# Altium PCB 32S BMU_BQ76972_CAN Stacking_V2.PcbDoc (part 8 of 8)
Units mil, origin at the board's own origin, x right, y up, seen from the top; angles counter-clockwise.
Board outline 7319.29 x 5216.54 mil, 4 copper layers (Top Layer, Layer 1, Layer 2, Bottom Layer), stack 73.068 mil thick; 811 components, 524 nets, 2320 pads, 2669 vias.
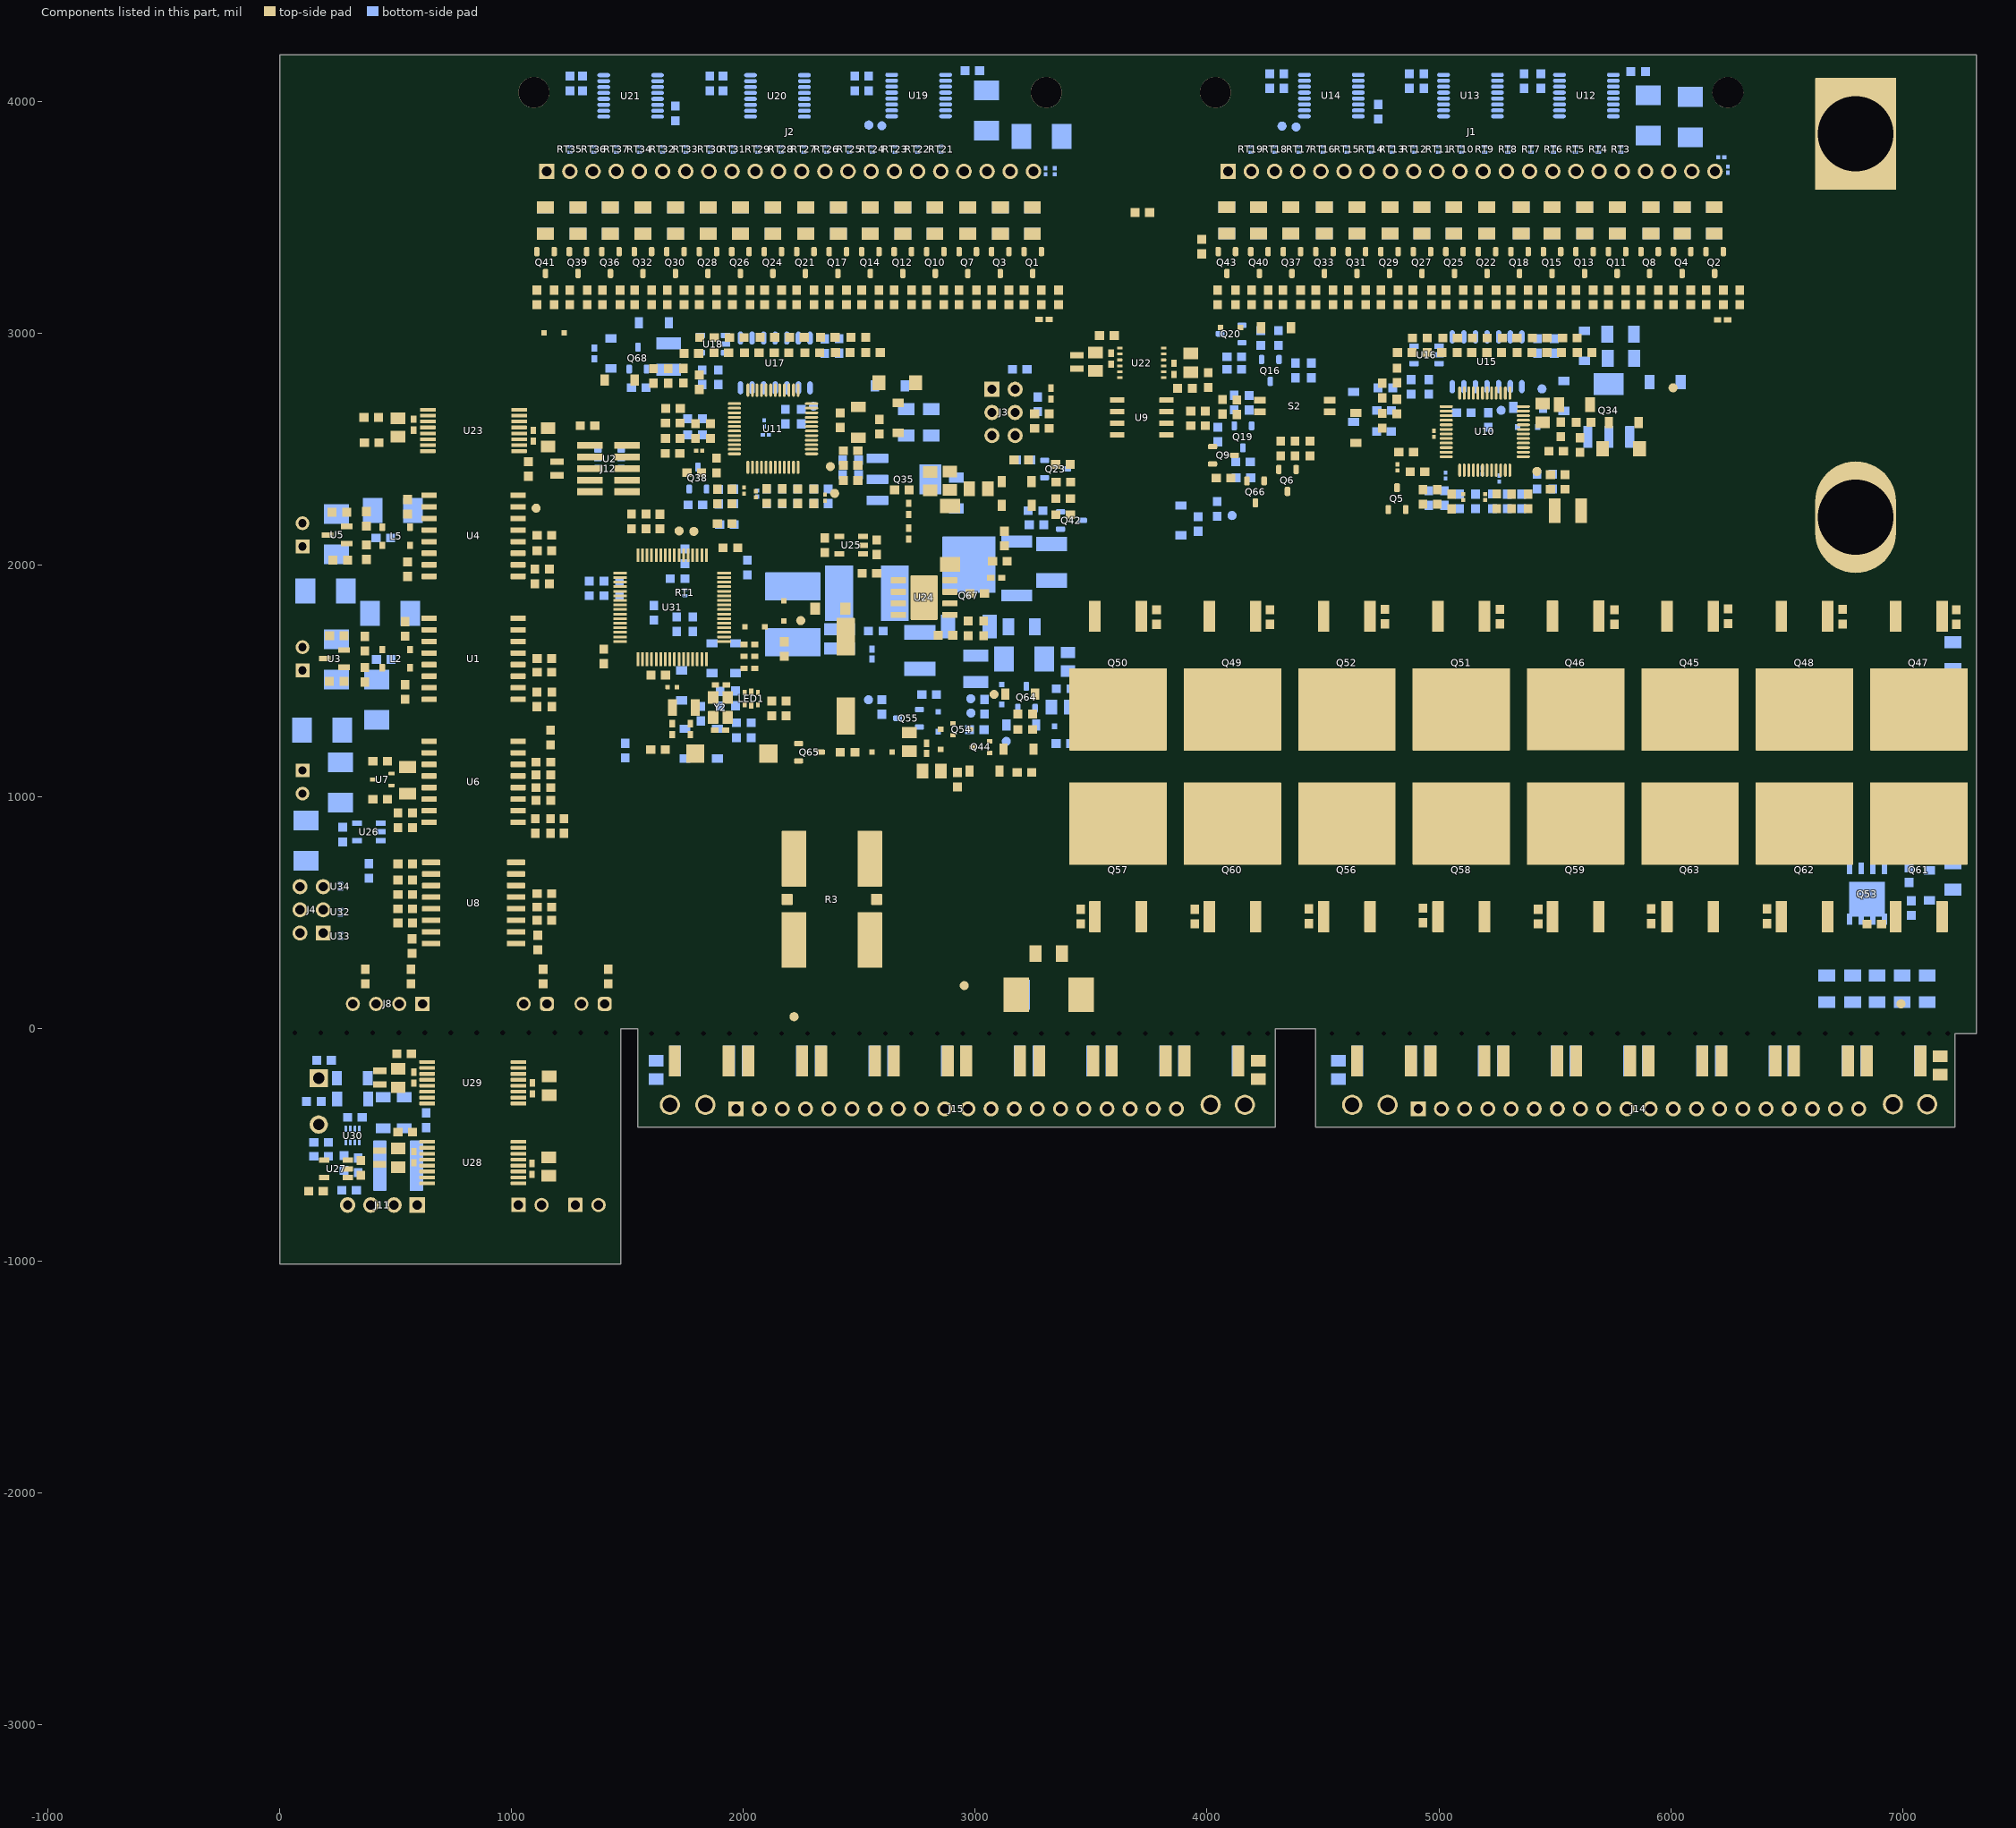
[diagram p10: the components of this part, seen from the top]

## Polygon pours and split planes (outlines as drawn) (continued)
NetQ8_3 on Bottom Layer "BOTTOM_LAYER_NETQ8_3_P371" (solid, remove dead copper, pour order 371): 6006.01,3285.78 5875.74,3285.78 5875.74,3481.81 6006.01,3481.81
NetQ4_3 on Bottom Layer "BOTTOM_LAYER_NETQ4_3_P372" (solid, remove dead copper, pour order 372): 6140.57,3285.78 6010.31,3285.78 6010.31,3481.81 6140.57,3481.81
NetQ2_3 on Bottom Layer "BOTTOM_LAYER_NETQ2_3_P373" (solid, remove dead copper, pour order 373): 6270.53,3285.78 6148.98,3285.78 6148.98,3481.81 6270.53,3481.81
Cell17 on Bottom Layer "BOTTOM_LAYER_CELL17_P389" (solid, remove dead copper, pour order 389): 4046.5,3651.57 4171.16,3651.57 4171.16,3504.92 4046.5,3504.92
Cell18 on Bottom Layer "BOTTOM_LAYER_CELL18_P390" (solid, remove dead copper, pour order 390): 4183.33,3651.57 4307.98,3651.57 4307.98,3504.92 4183.33,3504.92
Cell19 on Bottom Layer "BOTTOM_LAYER_CELL19_P391" (solid, remove dead copper, pour order 391): 4322.96,3651.57 4447.61,3651.57 4447.61,3504.92 4322.96,3504.92
Cell20 on Bottom Layer "BOTTOM_LAYER_CELL20_P392" (solid, remove dead copper, pour order 392): 4467.7,3651.57 4592.36,3651.57 4592.36,3504.92 4467.7,3504.92
Cell21 on Bottom Layer "BOTTOM_LAYER_CELL21_P393" (solid, remove dead copper, pour order 393): 4607.97,3651.57 4732.62,3651.57 4732.62,3504.92 4607.97,3504.92
Cell22 on Bottom Layer "BOTTOM_LAYER_CELL22_P394" (solid, remove dead copper, pour order 394): 4750.88,3651.57 4875.54,3651.57 4875.54,3504.92 4750.88,3504.92
Cell23 on Bottom Layer "BOTTOM_LAYER_CELL23_P409" (solid, remove dead copper, pour order 409): 4888.49,3651.57 5013.15,3651.57 5013.15,3504.92 4888.49,3504.92
Cell24 on Bottom Layer "BOTTOM_LAYER_CELL24_P415" (solid, remove dead copper, pour order 415): 5025.86,3651.57 5150.52,3651.57 5150.52,3504.92 5025.86,3504.92
Cell25 on Bottom Layer "BOTTOM_LAYER_CELL25_P416" (solid, remove dead copper, pour order 416): 5167.05,3651.57 5291.7,3651.57 5291.7,3504.92 5167.05,3504.92
Cell26 on Bottom Layer "BOTTOM_LAYER_CELL26_P420" (solid, remove dead copper, pour order 420): 5316.58,3651.57 5441.24,3651.57 5441.24,3504.92 5316.58,3504.92
Cell27 on Bottom Layer "BOTTOM_LAYER_CELL27_P427" (solid, remove dead copper, pour order 427): 5449.54,3616.02 5574.2,3616.02 5574.2,3504.92 5449.54,3504.92
Cell28 on Bottom Layer "BOTTOM_LAYER_CELL28_P434" (solid, remove dead copper, pour order 434): 5589.8,3616.02 5714.46,3616.02 5714.46,3504.92 5589.8,3504.92
Cell29 on Bottom Layer "BOTTOM_LAYER_CELL29_P445" (solid, remove dead copper, pour order 445): 5731.78,3616.02 5856.44,3616.02 5856.44,3504.92 5731.78,3504.92
Cell30 on Bottom Layer "BOTTOM_LAYER_CELL30_P459" (solid, remove dead copper, pour order 459): 5876.03,3616.02 6000.68,3616.02 6000.68,3504.92 5876.03,3504.92
Cell31 on Bottom Layer "BOTTOM_LAYER_CELL31_P466" (solid, remove dead copper, pour order 466): 6010.59,3616.02 6135.25,3616.02 6135.25,3504.92 6010.59,3504.92
Cell32 on Bottom Layer "BOTTOM_LAYER_CELL32_P468" (solid, remove dead copper, pour order 468): 6152.59,3620.67 6277.25,3620.67 6277.25,3509.57 6152.59,3509.57
Cell14 on Bottom Layer "BOTTOM_LAYER_CELL14_P386" (solid, remove dead copper, pour order 386): 2929.27,3615.04 3053.92,3615.04 3053.92,3494.09 2929.27,3494.09
5V_EXT on Bottom Layer "Bottom Layer-5V_EXT" (solid, remove dead copper, pour order 250): 631.98,-701.89 659.54,-674.33 659.54,-404.06 409.55,-404.06 409.55,-450.37 521.12,-561.94 521.12,-671.7 552.06,-702.63 552.06,-789.85 562.59,-800.38 628.18,-800.38 631.98,-796.58
GND_SYS_EXT on Bottom Layer "BOTTOM_LAYER_GND_SYS_EXT_P473" (solid, remove dead copper, pour order 473): 9.6,-39.88 664.29,-39.88 664.29,-994.6 9.25,-994.6
GND_EXT on Bottom Layer "BOTTOM_LAYER_GND_EXT_P474" (solid, remove dead copper, pour order 474): 999.79,-39.88 1447.73,-39.88 1447.73,-411.82 999.66,-411.82
UP_GND_EXT on Bottom Layer "BOTTOM_LAYER_UP_GND_EXT_P475" (solid, remove dead copper, pour order 475): 999.72,-420.64 1447.73,-420.64 1447.73,-994.6 999.51,-994.6
NetC115_1 on Bottom Layer "BOTTOM_LAYER_NETC115_1_P333" (solid, remove dead copper, pour order 333): 3327.79,2944.59 3397.93,2944.59 3415.35,2927.17 3415.35,2907.48 3385.83,2877.95 3327.79,2877.95
2V5BOT on Bottom Layer "BOTTOM_LAYER_2V5BOT_P253" (solid, remove dead copper, pour order 253): 2215.65,3013.58 2235.55,3033.48 2425.31,3033.48 2440.39,3018.4 2439.58,3017.59 2439.58,2947.11 2302.43,2947.11 2302.85,2946.69 2302.85,2740.39 2271.68,2740.39 2264.36,2747.71 2264.66,2748 2264.66,2931.11 2247.1,2948.66 2215.65,2948.66
NetQ1_3 on Bottom Layer "BOTTOM_LAYER_NETQ1_3_P356" (solid, remove dead copper, pour order 356): 3338.02,3277.56 3207.75,3277.56 3207.75,3480.83 3338.02,3480.83
Cell16 on Bottom Layer "BOTTOM_LAYER_CELL16_P388" (solid, remove dead copper, pour order 388): 3208.04,3651.57 3332.69,3651.57 3332.69,3494.09 3208.04,3494.09
Cell15 on Bottom Layer "BOTTOM_LAYER_CELL15_P387" (solid, remove dead copper, pour order 387): 3069.38,3615.04 3194.03,3615.04 3194.03,3494.09 3069.38,3494.09
Cell13 on Bottom Layer "BOTTOM_LAYER_CELL13_P385" (solid, remove dead copper, pour order 385): 2787.21,3615.04 2911.86,3615.04 2911.86,3494.09 2787.21,3494.09
Cell12 on Bottom Layer "BOTTOM_LAYER_CELL12_P384" (solid, remove dead copper, pour order 384): 2649.28,3615.04 2773.94,3615.04 2773.94,3494.09 2649.28,3494.09
Cell11 on Bottom Layer "BOTTOM_LAYER_CELL11_P383" (solid, remove dead copper, pour order 383): 2508.96,3615.04 2633.61,3615.04 2633.61,3494.09 2508.96,3494.09
Cell10 on Bottom Layer "BOTTOM_LAYER_CELL10_P382" (solid, remove dead copper, pour order 382): 2370.8,3651.57 2495.46,3651.57 2495.46,3503.94 2370.8,3503.94
Cell9 on Bottom Layer "BOTTOM_LAYER_CELL9_P381" (solid, remove dead copper, pour order 381): 2230.7,3651.57 2355.35,3651.57 2355.35,3503.94 2230.7,3503.94
Cell8 on Bottom Layer "BOTTOM_LAYER_CELL8_P380" (solid, remove dead copper, pour order 380): 2088.62,3651.57 2213.28,3651.57 2213.28,3503.94 2088.62,3503.94
Cell7 on Bottom Layer "BOTTOM_LAYER_CELL7_P379" (solid, remove dead copper, pour order 379): 1949.12,3651.57 2073.77,3651.57 2073.77,3503.94 1949.12,3503.94
Cell6 on Bottom Layer "BOTTOM_LAYER_CELL6_P378" (solid, remove dead copper, pour order 378): 1810.37,3651.57 1935.03,3651.57 1935.03,3503.94 1810.37,3503.94
Cell5 on Bottom Layer "BOTTOM_LAYER_CELL5_P377" (solid, remove dead copper, pour order 377): 1668.3,3651.57 1792.95,3651.57 1792.95,3503.94 1668.3,3503.94
Cell4 on Bottom Layer "BOTTOM_LAYER_CELL4_P376" (solid, remove dead copper, pour order 376): 1528.19,3651.57 1652.84,3651.57 1652.84,3503.94 1528.19,3503.94
Cell3 on Bottom Layer "BOTTOM_LAYER_CELL3_P375" (solid, remove dead copper, pour order 375): 1387.8,3651.57 1512.45,3651.57 1512.45,3503.94 1387.8,3503.94
Cell2 on Bottom Layer "BOTTOM_LAYER_CELL2_P374" (solid, remove dead copper, pour order 374): 1247.97,3651.57 1372.63,3651.57 1372.63,3503.94 1247.97,3503.94
Cell1 on Bottom Layer "BOTTOM_LAYER_CELL1_P340" (solid, remove dead copper, pour order 340): 1023.62,3651.57 1232.52,3651.57 1232.52,3503.94 1023.62,3503.94
NetQ3_3 on Bottom Layer "BOTTOM_LAYER_NETQ3_3_P355" (solid, remove dead copper, pour order 355): 3199.36,3277.56 3069.09,3277.56 3069.09,3480.83 3199.36,3480.83
NetQ7_3 on Bottom Layer "BOTTOM_LAYER_NETQ7_3_P354" (solid, remove dead copper, pour order 354): 3059.25,3277.56 2928.98,3277.56 2928.98,3480.83 3059.25,3480.83
NetQ10_3 on Bottom Layer "BOTTOM_LAYER_NETQ10_3_P353" (solid, remove dead copper, pour order 353): 2917.19,3277.56 2786.92,3277.56 2786.92,3480.83 2917.19,3480.83
NetQ12_3 on Bottom Layer "BOTTOM_LAYER_NETQ12_3_P352" (solid, remove dead copper, pour order 352): 2779.27,3277.56 2649,3277.56 2649,3480.83 2779.27,3480.83
NetQ14_3 on Bottom Layer "BOTTOM_LAYER_NETQ14_3_P351" (solid, remove dead copper, pour order 351): 2638.94,3277.56 2508.67,3277.56 2508.67,3480.83 2638.94,3480.83
NetQ17_3 on Bottom Layer "BOTTOM_LAYER_NETQ17_3_P350" (solid, remove dead copper, pour order 350): 2500.79,3277.56 2370.52,3277.56 2370.52,3480.83 2500.79,3480.83
NetQ21_3 on Bottom Layer "BOTTOM_LAYER_NETQ21_3_P349" (solid, remove dead copper, pour order 349): 2360.68,3277.56 2230.41,3277.56 2230.41,3480.83 2360.68,3480.83
NetQ24_3 on Bottom Layer "BOTTOM_LAYER_NETQ24_3_P348" (solid, remove dead copper, pour order 348): 2218.6,3277.56 2088.34,3277.56 2088.34,3480.83 2218.6,3480.83
NetQ26_3 on Bottom Layer "BOTTOM_LAYER_NETQ26_3_P347" (solid, remove dead copper, pour order 347): 2079.1,3277.56 1948.83,3277.56 1948.83,3480.83 2079.1,3480.83
NetQ28_3 on Bottom Layer "BOTTOM_LAYER_NETQ28_3_P346" (solid, remove dead copper, pour order 346): 1940.35,3277.56 1810.09,3277.56 1810.09,3480.83 1940.35,3480.83
NetQ30_3 on Bottom Layer "BOTTOM_LAYER_NETQ30_3_P345" (solid, remove dead copper, pour order 345): 1798.28,3277.56 1668.01,3277.56 1668.01,3480.83 1798.28,3480.83
NetQ32_3 on Bottom Layer "BOTTOM_LAYER_NETQ32_3_P344" (solid, remove dead copper, pour order 344): 1658.17,3277.56 1527.9,3277.56 1527.9,3480.83 1658.17,3480.83
NetQ36_3 on Bottom Layer "BOTTOM_LAYER_NETQ36_3_P343" (solid, remove dead copper, pour order 343): 1517.78,3277.56 1387.51,3277.56 1387.51,3480.83 1517.78,3480.83
NetQ39_3 on Bottom Layer "BOTTOM_LAYER_NETQ39_3_P342" (solid, remove dead copper, pour order 342): 1377.95,3277.56 1247.69,3277.56 1247.69,3480.83 1377.95,3480.83
NetQ41_3 on Bottom Layer "BOTTOM_LAYER_NETQ41_3_P249" (solid, remove dead copper, pour order 249): 1232.52,3277.56 1023.62,3277.56 1023.62,3480.83 1232.52,3480.83
GND_SYS on Bottom Layer "BOTTOM_LAYER_GND_SYS_P341" (solid, remove dead copper, pour order 341): 9.84,4192.91 669.29,4192.91 669.29,9.84 9.84,9.84
NetC123_1 on Bottom Layer "BOTTOM_LAYER_NETC123_1_P336" (solid, remove dead copper, pour order 336): 2494.86,1696.64 2345.86,1696.64 2345.86,2002.43 2494.86,2002.43
UP_GND on Layer 1 "LAYER_1_UP_GND_P499" (solid, remove dead copper, pour order 499): 3800.73,2175.2 3800.73,4202.76 6285.83,4202.76 6316.42,4172.17 6316.42,2487.95 5917.57,2487.95 5688.72,2175.2
GND on Layer 1 "LAYER_1_GND_P493" (solid, remove dead copper, pour order 493): 1003.94,19.69 3426.18,19.69 3426.18,2102.3 3472.81,2147.49 3633.6,2149.66 3633.6,4192.64 1003.94,4192.64
NetC110_2 on Layer 1 "Top Layer-NetC110_2" (solid, remove dead copper, pour order 244): 3486.43,1654.42 7233.34,1654.42 7298.9,1719.98 7298.9,2480.03 5920.68,2480.03 5690.06,2165.35 3517.45,2165.35 3439.22,2087.13 3439.22,1701.63
PACK+ on Layer 1 "LAYER_1_PACK+_P488" (solid, remove dead copper, pour order 488): 3356.69,624.52 7244,624.52 7298.9,569.62 7298.9,74.49 7249.68,25.27 3336.39,25.27 3336.86,604.69
NetD24_1 on Layer 1 "LAYER_1_NETD24_1_P497" (solid, remove dead copper, pour order 497): 3371.59,1633.88 3346.76,1609.05 3346.76,665.72 3372.72,639.76 7233.49,639.76 7298.9,705.17 7298.9,1567.99 7291.85,1567.99 7227.98,1631.87
BAT+ on Layer 1 "LAYER_1_BAT+_P496" (solid, remove dead copper, pour order 496): 6344.88,4162.32 6385.31,4202.76 7229.65,4202.76 7309.45,4122.95 7309.45,2598.29 7280.06,2568.9 6375.75,2568.9 6344.88,2599.76
GND_SYS_EXT on Layer 1 "LAYER_1_GND_SYS_EXT_P442" (solid, remove dead copper, pour order 442): 9.6,-39.88 658.92,-39.88 658.92,-994.6 9.25,-994.6
UP_GND_EXT on Layer 1 "LAYER_1_UP_GND_EXT_P443" (solid, remove dead copper, pour order 443): 999.72,-420.64 1447.73,-420.64 1447.73,-994.6 999.51,-994.6
GND_EXT on Layer 1 "LAYER_1_GND_EXT_P463" (solid, remove dead copper, pour order 463): 999.79,-39.88 1447.73,-39.88 1447.73,-411.82 999.66,-411.82
GND_SYS on Layer 1 "LAYER_1_GND_SYS_P421" (solid, remove dead copper, pour order 421): 9.84,4192.91 669.29,4192.91 669.29,9.84 9.84,9.84
UP_GND on Layer 2 "LAYER_2_UP_GND_P512" (solid, remove dead copper, pour order 512): 3800.73,2175.2 3800.73,4202.76 6285.83,4202.76 6316.42,4172.17 6316.42,2487.95 5917.57,2487.95 5688.72,2175.2
GND on Layer 2 "LAYER_2_GND_P509" (solid, remove dead copper, pour order 509): 1003.94,19.69 3426.18,19.69 3426.18,2102.3 3472.81,2147.49 3633.6,2149.66 3633.6,4192.64 1003.94,4192.64
NetC110_2 on Layer 2 "Top Layer-NetC110_2" (solid, remove dead copper, pour order 506): 3486.43,1654.42 7233.34,1654.42 7298.9,1719.98 7298.9,2480.03 5920.68,2480.03 5690.06,2165.35 3517.45,2165.35 3439.22,2087.13 3439.22,1701.63
PACK+ on Layer 2 "LAYER_2_PACK+_P503" (solid, remove dead copper, pour order 503): 3356.69,624.52 7244,624.52 7298.9,569.62 7298.9,74.49 7249.68,25.27 3336.39,25.27 3336.86,604.69
NetC110_2 on Layer 2 "Top Layer-NetC110_2" (solid, remove dead copper, pour order 267): 3758.93,1654.42 7233.34,1654.42 7298.9,1719.98 7298.9,2480.03 5920.68,2480.03 5708.61,2190.66 3793.2,2190.66 3705.12,2102.57 3705.12,1708.23
BAT+ on Layer 2 "LAYER_2_BAT+_P461" (solid, remove dead copper, pour order 461): 6344.88,4162.32 6385.31,4202.76 7229.65,4202.76 7309.45,4122.95 7309.45,2598.4 7279.95,2568.9 6374.76,2568.9 6344.88,2598.78
GND_SYS_EXT on Layer 2 "LAYER_2_GND_SYS_EXT_P444" (solid, remove dead copper, pour order 444): 9.6,-39.88 658.92,-39.88 658.92,-994.6 9.25,-994.6
UP_GND_EXT on Layer 2 "LAYER_2_UP_GND_EXT_P446" (solid, remove dead copper, pour order 446): 999.72,-420.64 1447.73,-420.64 1447.73,-994.6 999.51,-994.6
GND_EXT on Layer 2 "LAYER_2_GND_EXT_P448" (solid, remove dead copper, pour order 448): 999.79,-39.88 1447.73,-39.88 1447.73,-411.82 999.66,-411.82
GND_SYS on Layer 2 "LAYER_2_GND_SYS_P426" (solid, remove dead copper, pour order 426): 9.84,4192.54 669.29,4192.54 669.29,9.84 9.84,9.84

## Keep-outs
Top Layer:
  lines w10: 456.17,1015.38 456.17,1129.55 ; 477.56,627.26 478.19,467.49 ; 1630.14,2566.58 1630.14,2589.6
Bottom Layer:
  lines w10: 2547.59,1654.74 2547.59,1694.46 ; 3383.92,1567.77 3383.92,1607.49
Keep-Out Layer:
  text ".Layer_Name" at 143.93,-2531.72 h30

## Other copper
Top Layer:
  region net NetC13_2: 3088.64,1924.53 3078.45,1914.33 2851.51,1914.33 2851.51,1967.14 2851.11,1967.55 2697.85,1967.55 2697.85,2127.83 2697.55,2128.13 2699.05,2129.63 2935.09,2129.63 2962.6,2102.13 3088.64,2102.13
  region net NetD24_1: 3346.76,665.72 3372.72,639.76 7233.49,639.76 7298.9,705.17 7298.9,1567.99 7227.98,1631.87 3371.59,1633.88 3346.76,1597.9
  region net PACK-: 2381.89,1064.84 2381.89,605.52 2612.8,605.52 2622.62,595.7 2622.62,517.89 2614.75,510.02 2382.12,510.02 2381.89,510.25 2381.89,19.69 3307.09,19.69 3307.09,1064.84
  region net Current+: 2368.41,1063.6 1454.78,1063.6 1454.78,20.39 2368.41,20.39 2368.41,509.7 2367.86,510.25 2148.7,510.25 2143.18,515.76 2143.18,600.01 2148.7,605.52 2368.41,605.52
  region net NetC128_1: 2700.4,1900.13 2596.76,1900.13 2596.76,1985.74 2546.23,1985.74 2546.23,1900.13 2486.21,1840.11 2419.91,1840.11 2389.47,1809.67 2389.47,1597.9 2487.96,1597.9 2487.96,1777.73 2572.36,1862.13 2700.4,1862.13
  pour cut-out: 5117.58,3372.92 5155.94,3372.92 5155.94,3094.13 5117.59,3094.13
  pour cut-out: 4981.02,3372.92 5019.37,3372.92 5019.37,3094.13 4981.03,3094.13
  pour cut-out: 6101.89,3372.92 6140.24,3372.92 6140.24,3094.13 6101.9,3094.13
  pour cut-out: 1619.47,3377.58 1657.83,3377.58 1657.83,3094.13 1619.48,3094.13
  pour cut-out: 2883.87,3378.86 2908.43,3354.31 2908.43,3094.13 2882.35,3094.13
  pour cut-out: 482.23,-676.39 469.23,-663.38 469.23,-607.44
  pour cut-out: 372.29,-529.19 374.79,-476.87 399.55,-476.87
  pour cut-out: 372.59,-331.32 440.37,-263.54 470.25,-263.54
  pour cut-out: 365.39,-132.39 384.8,-256.69 328.45,-313.04
  pour cut-out: 365.39,-148.79 365.39,-132.39 397.98,-132.39
  pour cut-out: 3476.94,2882.36 3477.53,2882.95 3477.76,2882.72 3477.76,2823.99 3474.07,2820.3 3357.72,2820.3 3350.81,2827.2 3350.81,2882.36
  pour cut-out: 1157.54,2421.98 1158.92,2423.36 1234.36,2423.36 1234.36,2411.86 1157.27,2411.86
  pour cut-out: 389.29,2596.07 389.29,2557.65 395.14,2557.65 401.12,2599.53
  pour cut-out: 587.46,2598.75 590.53,2601.83 607.66,2601.83
  pour cut-out: 2155.51,600.39 2156.8,599.11 2598.43,599.11 2598.43,516.72 2597.25,517.89 2155.51,517.89
  text ".Layer_Name" at 143.93,-2531.72 h30
Layer 1:
  region net PACK-: 2381.89,1190.79 2381.89,605.52 2612.8,605.52 2622.62,595.7 2622.62,517.89 2614.75,510.02 2382.12,510.02 2381.89,510.25 2381.89,19.69 3307.09,19.69 3307.09,1190.79
  region net Current+: 2368.41,1190.79 1454.78,1190.79 1454.78,20.39 2368.41,20.39 2368.41,509.7 2367.86,510.25 2148.7,510.25 2143.18,515.76 2143.18,600.01 2148.7,605.52 2368.41,605.52
  pour cut-out: 2155.51,600.39 2156.8,599.11 2598.43,599.11 2598.43,516.72 2597.25,517.89 2155.51,517.89
Layer 2:
  region net NetD24_1: 3346.76,665.72 3372.72,639.76 7233.49,639.76 7298.9,705.17 7298.9,1567.99 7231.5,1635.39 7227.98,1631.87 3371.59,1633.88 3346.76,1597.9
  region net PACK-: 2417.95,1190.94 2417.95,605.52 2612.8,605.52 2622.62,595.7 2622.62,517.89 2614.75,510.02 2382.12,510.02 2381.89,510.25 2381.89,19.69 3307.09,19.69 3307.09,1190.94
  region net Current+: 2352.36,1190.79 1454.78,1190.79 1454.78,20.39 2368.41,20.39 2368.41,509.7 2367.86,510.25 2148.7,510.25 2143.18,515.76 2143.18,600.01 2148.7,605.52 2352.36,605.52
  pour cut-out: 2155.51,600.39 2156.8,599.11 2598.43,599.11 2598.43,516.72 2597.25,517.89 2155.51,517.89
Bottom Layer:
  region net Current+: 2368.41,1191.3 1454.78,1191.3 1454.78,20.39 2368.41,20.39 2368.41,509.7 2367.86,510.25 2148.7,510.25 2143.18,515.76 2143.18,600.01 2148.7,605.52 2368.41,605.52
  pour cut-out: 3441.39,1631.16 3441.39,1185.2 3348.71,1092.52 3319.2,1122.03 3319.2,1436.35
  region net BAT_IN: 3111.81,1975.98 3111.81,1839.82 3393.7,1839.82 3393.7,1975.98
  region net NetC120_1: 3169.98,1540.74 3169.98,1778.78 3153.02,1795.73 2981.05,1795.73 2936.47,1751.16 2936.47,1557.14 2952.88,1540.74
  region net PACK-: 2381.89,1193.85 2381.89,605.52 2612.8,605.52 2622.62,595.7 2622.62,517.89 2614.75,510.02 2382.12,510.02 2381.89,510.25 2381.89,19.69 3307.09,19.69 3307.09,1193.85
  pour cut-out: 2155.51,600.39 2156.8,599.11 2598.43,599.11 2598.43,516.72 2597.25,517.89 2155.51,517.89
  text ".Layer_Name" at 143.93,-2531.72 h30

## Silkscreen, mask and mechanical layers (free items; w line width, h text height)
Top Overlay:
  lines w10: 876.36,842.3 994.09,842.3 ; 876.36,1376.12 994.09,1376.12 ; 876.36,1902.03 994.09,1902.03 ; 1385.97,2544.9 1423.76,2582.69 1423.76,2595.44 ; 1564.17,2325.77 1564.17,2326.96 1591.54,2354.32
  text "TOP_AFE Cell1-16" at 6363.42,4157.32 h30 r270
  text "BOT_AFE Cell1-16" at 3430.35,4108.74 h30 r270
  text "BAT+" at 6622.03,4033.94 h30
  text "TIDA-010247 / 48V-1500V Stackable BMU" at 157.48,3799.21 h40
  text "UP_GND" at 6054.27,2752.62 h30
  text "RST" at 1406.94,2606.68 h30
  text "GND" at 1607.01,2434.14 h30 r90
  text "PIN1" at 1596.54,2359.32 h30
  text "3V3" at 1583.82,2303.73 h30
  text "CANL" at 39.53,2251.34 h30
  text "SWCLK" at 1269.86,2230.98 h30
  text "SWDIO" at 1274.86,2183.23 h30
  text "CANH" at 44.37,1993.19 h30
  text "CANL" at 49.37,1728.12 h30
  text "CANH" at 42.74,1445.01 h30
  text "485A" at 59.21,1179.77 h30
  text "MCU RESET" at 1550.28,1083.82 h30
  text "485B" at 54.37,920.35 h30
  text "SHUNT" at 2323.91,871.47 h30
  text "WAKEIN" at 140.36,793.83 h30
  text "WAKEOUT" at 142.74,743.93 h30
  text "PWMFAN" at 142.74,698.66 h30
  text "GND_SYS" at 37.5,280.75 h30
  text "5V_ISO" at 627.14,173.05 h30
  text "3V3_ISO" at 83.74,93.74 h30
  text "PACK+" at 6819.42,93.58 h30
  text "3V3" at 910.51,83.74 h30
  text "PACK-" at 2868.23,72.23 h30
  text "3V3_TOP" at 1481.38,60.06 h30
  text "Current+" at 1904.61,54.21 h30
  text "Power rail#2 card / For 24V external input" at 1258.08,-161.06 h30 r270
  text ".Layer_Name" at 143.93,-2531.72 h30
Bottom Overlay:
  lines w10: 1237.4,3759.84 1262.6,3759.84 ; 2049.05,3759.84 2074.26,3759.84 ; 2841.73,3759.84 2866.93,3759.84 ; 4177.27,3759.84 4202.48,3759.84 ; 5078.74,3759.84 5103.95,3759.84 ; 5772.04,3759.84 5797.24,3759.84
  text ".Layer_Name" at 143.93,-2531.72 h30
Top Paste:
  text ".Layer_Name" at 143.93,-2531.72 h30
Bottom Paste:
  text ".Layer_Name" at 143.93,-2531.72 h30
Top Solder:
  region: 6590.23,2472.81 7014.17,2472.81 7014.17,1966.95 6590.23,1966.95
  region: 6590.23,4132.66 7014.17,4132.66 7014.17,3620.5 6590.23,3620.5
  text ".Layer_Name" at 143.93,-2531.72 h30
  text ".Layer_Name" at 143.93,-2531.72 h30
Bottom Solder:
  rectangle: 6344.88,2568.9 7299.61,4183.07
  region: 2381.89,1193.85 2381.89,605.52 2612.8,605.52 2622.62,595.7 2622.62,517.89 2614.75,510.02 2382.12,510.02 2381.89,510.25 2381.89,19.69 3307.09,19.69 3307.09,1193.85
  region: 2368.41,1141.73 1454.78,1141.73 1454.78,20.39 2368.41,20.39 2368.41,509.7 2367.86,510.25 2148.7,510.25 2143.18,515.76 2143.18,600.01 2148.7,605.52 2368.41,605.52
  region: 3336.61,403.54 6418.89,403.54 6448.42,374.02 6448.42,25.27 3336.39,25.27
  region: 7135.83,1633.84 7135.83,1624.02 7135.83,756.09 6737.69,756.09 6711.13,729.52 6711.13,639.76 3480.76,639.76 3464.57,659.45 3464.57,702.31 3464.57,1633.84
  region: 7298.9,2480.03 7298.9,1860.24 3848.43,1860.24 3848.43,2102.3 4011.71,2102.3 4074.77,2165.35 5685.79,2165.35 5920.68,2480.03
  text ".Layer_Name" at 143.93,-2531.72 h30
Drill Guide:
  text ".Layer_Name" at 143.93,-2531.72 h30
M1 Board Outline:
  lines w10: 0,-1013.78 1470.69,-1013.78 1470.69,0 1545.28,0 1545.28,-423.54 4293.61,-423.54 4293.61,-39.37 4293.61,0 4468.5,0 4468.5,-423.54 7226.68,-423.54 7226.68,-19.68 7319.29,-19.68 7319.29,4202.76 7299.61,4202.76 0,4202.76 0,0 0,-1013.78
  text ".Layer_Name" at 143.93,-2531.72 h30
M2 Board Dimensions:
  rectangle: -433.07,-1948.23 -308.07,-1823.23
  rectangle: -308.07,-2073.23 66.93,-1948.23
  lines w7: -433.07,-1948.23 566.93,-1948.23 ; -308.07,-2073.23 -308.07,-1823.23 ; -183.07,-2073.23 -183.07,-1823.23 ; 66.93,-2073.23 66.93,-1823.23 ; 316.93,-2073.23 316.93,-1823.23 ; -433.07,-2073.23 566.93,-2073.23 566.93,-1823.23 -433.07,-1823.23 -433.07,-2073.23
  text ".Layer_Name" at 143.93,-2531.72 h30
M3 3D STEP Top:
  text ".Layer_Name" at 143.93,-2531.72 h30
M4 3D STEP Bottom:
  text ".Layer_Name" at 143.93,-2531.72 h30
M5 Assembly Top:
  lines w10: -725.07,-2603.4 5874.93,-2603.4 ; -725.07,-2400.06 5876.93,-2400.06 ; -725.07,-2196.73 -725.07,-2806.73 3279.93,-2806.73 5876.93,-2806.73 5876.93,-2196.73 -724.57,-2196.73 -724.57,-2806.73 850.93,-2806.73 ; 1739.93,-2806.73 1739.93,-2196.73 ; 3006.93,-2400.06 3006.93,-2196.73 ; 3846.93,-2400.06 3846.93,-2196.73 ; 4468.93,-2813.23 4468.93,-2610.4
  text "COMPONENTS MARKED 'DNP' SHOULD NOT BE POPULATED." at 720.43,-1991.73 h30
  text "ASSEMBLY VARIANT:" at 719.93,-2107.23 h30
  text ".VariantName" at 1755.93,-2107.23 h30
  text "PCB VIEWED FROM TOP SIDE" at -661.57,-2328.9 h30
  text "BOARD #:" at 1814.93,-2328.9 h30
  text ".PRJ_Number" at 2360.43,-2328.9 h30
  text "REV:" at 3204.93,-2328.9 h30
  text ".PCB_Rev" at 3496.43,-2328.9 h30
  text "SVN REV:" at 4042.93,-2328.9 h30
  text ".VersionControl_RevNumber" at 4548.93,-2328.9 h30
  text "TID #:" at 1814.93,-2532.23 h30
  text ".TID" at 2360.43,-2532.23 h30
  text "PLOT NAME =" at -661.57,-2737.56 h30
  text ".plot_File_Name" at 143.93,-2737.56 h30
  text "GENERATED    :" at 1816.93,-2737.56 h30
  text ".Print_Date" at 2686.43,-2737.56 h30
  text ".Print_Time" at 3415.43,-2737.56 h30
  text "TEXAS INSTRUMENTS" at 4679.93,-2737.56 h30
M6 Assembly Bottom:
  lines w10: -725.57,-2400.56 5876.43,-2400.56 ; -723.57,-2603.9 5876.43,-2603.9 ; 682.43,-2813.73 682.43,-2610.9 ; 1304.43,-2400.56 1304.43,-2197.23 ; 2144.43,-2400.56 2144.43,-2197.23 ; 3411.43,-2807.23 3411.43,-2197.23 ; 4300.43,-2807.23 5875.93,-2807.23 5875.93,-2197.23 -725.57,-2197.23 -725.57,-2807.23 1871.43,-2807.23 5876.43,-2807.23 5876.43,-2197.23
  text "COMPONENTS MARKED 'DNP' SHOULD NOT BE POPULATED." at 5668.93,-1991.23 h30
  text ".VariantName" at 4624.93,-2107.23 h30
  text "ASSEMBLY VARIANT:" at 5663.93,-2107.23 h30
  text ".VersionControl_RevNumber" at 602.43,-2329.4 h30
  text "SVN REV:" at 1108.43,-2329.4 h30
  text ".PCB_Rev" at 1654.93,-2329.4 h30
  text "REV:" at 1946.43,-2329.4 h30
  text ".PRJ_Number" at 2790.93,-2329.4 h30
  text "BOARD #:" at 3336.43,-2329.4 h30
  text "PCB VIEWED FROM BOTTOM SIDE" at 5812.93,-2329.4 h30
  text ".TID" at 2790.93,-2532.73 h30
  text "TID #:" at 3336.43,-2532.73 h30
  text "TEXAS INSTRUMENTS" at 471.43,-2738.06 h30
  text ".Print_Time" at 1735.93,-2738.06 h30
  text ".Print_Date" at 2464.93,-2738.06 h30
  text "GENERATED    :" at 3334.43,-2738.06 h30
  text ".plot_File_Name" at 5007.43,-2738.06 h30
  text "PLOT NAME =" at 5812.93,-2738.06 h30
M9 Title Sheet:
  drawing of 57 lines, arcs and shapes, not listed
  text "1" at 306.77,6363.27 h30
  text "2" at 2802.43,6363.27 h30
  text "3" at 5291.77,6363.27 h30
  text "4" at 7798.44,6363.27 h30
  text "5" at 10297.43,6363.27 h30
  text "6" at 12802.43,6363.27 h30
  text "A" at -849.57,5220.27 h30
  text "A" at 13950.43,5220.27 h30
  text "B" at -849.57,2840.27 h30
  text "B" at 13950.43,2840.27 h30
  text "C" at -849.57,465.27 h30
  text "C" at 13950.43,465.27 h30
  text "PROJECT TITLE:" at 10910.43,-1395.73 h30
  text ".PRJ_Title" at 10960.43,-1529.06 h30
  text "DESIGNED FOR:" at 10910.43,-1696.73 h30
  text ".PRJ_Customer" at 10960.43,-1836.73 h30
  text "D" at -849.57,-1904.73 h30
  text "D" at 13950.43,-1904.73 h30
  text "FILE NAME:" at 10910.43,-1996.73 h30
  text ".PCB_File_Name_No_Path" at 10960.43,-2116.73 h30
  text "Texas Instruments (TI) and/or its licensors do not warrant the accuracy or completeness of this specification" at 5940.93,-2278.57 h30
  text "ENGINEER:" at 10910.43,-2286.73 h30
  text "LAYOUT BY:" at 12415.43,-2286.73 h30
  text "or any information contained therein. TI and/or its licensors do not warrant that this design will meet" at 5895.94,-2391.23 h30
  text ".PRJ_Engineer" at 10960.43,-2441.72 h30
  text ".PCB_Layout" at 12465.93,-2441.72 h30
  text "the specifications, will be suitable for your application or fit for any particular purpose, or will operate in" at 5895.94,-2503.9 h30
  text ".Layer_Name" at 143.93,-2531.72 h30
  text "ALTIUM DESIGNER VERSION:" at 12415.43,-2596.73 h30
  text "an implementation. TI and/or its licensors do not warrant that the design is production worthy. You should" at 5895.94,-2616.56 h30
  text "completely validate and test your design implementation to confirm the system functionality for your application." at 5940.93,-2729.23 h30
  text ".print_Scale" at 10960.43,-2730.06 h30
  text ".Application_BuildNumber" at 12465.93,-2730.06 h30
  text "1" at 306.77,-2936.73 h30
  text "2" at 2802.43,-2936.73 h30
  text "3" at 5291.77,-2936.73 h30
  text "4" at 7798.44,-2936.73 h30
  text "5" at 10297.43,-2936.73 h30
  text "6" at 12802.43,-2936.73 h30
M10 Fab Notes:
  drawing of 189 lines, arcs and shapes, not listed
  text "DESIGN INFORMATION" at 11948.95,4682.95 h30
  text "MIN. TRACK WIDTH:" at 11304.39,4550.82 h30
  text "8" at 12400.63,4550.82 h30
  text "MIL" at 12555.39,4550.82 h30
  text "7.874" at 12234.25,4429.13 h30
  text "MIN. CLEARANCE:" at 11304.39,4426.69 h30
  text "MIL" at 12555.39,4426.69 h30
  text "MIN. VIA PAD SIZE:" at 11304.39,4302.57 h30
  text "24" at 12370.64,4302.57 h30
  text "MIL" at 12555.39,4302.57 h30
  text "0.05mm (2MIL)" at 11999.39,4172.67 h30
  text "MINIMUM ANNULAR RING" at 10975.16,4164.45 h30
  text "EXTERNAL" at 12707.39,4164.45 h30
  text "PER" at 11175.16,4054.32 h30
  text "IPC-D-275 CLASS 2 LEVEL C" at 11395.16,4054.32 h30
  text "MIL, HOLES" at 12883.39,3953.84 h30
  text "+/-" at 12490.93,3945.25 h30
  text "+/-" at 13344.93,3945.25 h30
  text "REGISTRATION TOLERANCES:" at 10975.16,3944.19 h30
  text "METAL" at 12174.93,3944.19 h30
  text "5" at 12751.13,3944.19 h30
  text "3" at 13584.13,3944.19 h30
  text "MIL" at 13700.39,3944.19 h30
  text "HOLE SIZE TOLERANCE (UNLESS OTHERWISE SPECIFIED):" at 10975.16,3845.88 h30
  text "+/-" at 13344.93,3843 h30
  text "3" at 13584.13,3841.94 h30
  text "MIL" at 13700.39,3841.94 h30
  text "MATERIAL:" at 10900.39,3704.29 h30
  text "FR-4 High Tg" at 11886.83,3575.77 h30
  text "X" at 11742.39,3567.78 h30
  text "FR-4" at 11321.39,3563.26 h30
  text "OTHER" at 12809.39,3563.26 h30
  text "62 MIL (1.6mm) +/-10%" at 11641.49,3420.23 h30
  text "X" at 11521.39,3417.78 h30
  text "THICKNESS:" at 10975.16,3412.01 h30
  text "OTHER" at 12926.39,3412.01 h30
  text "TOLERANCE:" at 10975.16,3273.69 h30
  text "X" at 11823.39,3273.69 h30
  text "ANSI IPC-6012 TYPE 3 CLASS 2" at 12001.4,3273.69 h30
  text "OTHER +/-" at 12001.39,3129.51 h30
  text "BOW & TWIST:" at 10975.16,2984.32 h30
  text "X" at 11823.39,2984.32 h30
  text "ANSI IPC-6012 TYPE 3 CLASS 2" at 12001.4,2984.32 h30
  text "OTHER +/-" at 12001.39,2837.62 h30
  text "DRILLING:" at 10900.39,2707 h30
  text "NC_DRILL FILES" at 12661.39,2601.81 h30
  text "REFERENCE:" at 10975.16,2597.88 h30
  text "X" at 11632.39,2597.78 h30
  text "AS SHOWN" at 11810.39,2597.88 h30
  text "X" at 12533.39,2597.88 h30
  text "OTHER" at 12959.39,2455.62 h30
  text "PTH COPPER THICKNESS:" at 10974.83,2452.09 h30
  text "X" at 12114.07,2452.09 h30
  text "20-30 um" at 12242.07,2452.09 h30
  text "BOARD FINISH:" at 10900.39,2304.5 h30
  text "SILKSCREEN:" at 11055.61,2194.37 h30
  text "X" at 12013.39,2194.37 h30
  text "TOP" at 12130.39,2194.37 h30
  text "X" at 12523.39,2194.37 h30
  text "BOTTOM" at 12641.39,2194.37 h30
  text "SILKSCREEN COLOR:" at 11055.61,2039.18 h30
  text "X" at 12012.39,2039.18 h30
  text "WHITE" at 12130.39,2039.18 h30
  text "OTHER" at 12641.39,2039.18 h30
  text "X" at 12143.39,1895.73 h30
  text "GREEN" at 12261.39,1895.73 h30
  text "OTHER" at 12879.39,1895.73 h30
  text "SOLDER RESIST COLOR:" at 11055.61,1888.87 h30
  text "X" at 12143.39,1741.48 h30
  text "MATTE" at 12261.39,1741.48 h30
  text "SEMI-GLOSS" at 12878.93,1740.84 h30
  text "IMMERSION GOLD (ENIG)" at 11961.39,1568.71 h30
  text "ENEPIG" at 13298.93,1561.49 h30
  text "SURFACE FINISH:" at 10900.39,1560.49 h30
  text "X" at 11783.39,1560.49 h30
  text "IMM. TIN/SILVER OR EQUIV" at 11229.93,1423.17 h30
  text "OTHER" at 12661.39,1419.24 h30
  text "ARRAY/PANEL:" at 10900.39,1263.86 h30
  text "CUT AND TRIM PER M1 BOARD OUTLINE" at 11961.39,1255.64 h30
  text "N.C. ROUTE" at 11961.39,1119.67 h30
  text "X" at 12649.39,1119.67 h30
  text "V. SCORE" at 12827.39,1119.67 h30
  text "CERTIFICATION:" at 10900.39,990.54 h30
  text "MATERIALS AND WORKMANSHIP FOR ALL PCBS" at 11625.39,990.54 h30
  text "TO MEET OR EXCEED THE REQUIREMENTS OF:" at 11625.39,896.48 h30
  text "X" at 11262.9,767.85 h30
  text "ANSI IPC-A-600F CLASS ->" at 11390.89,767.85 h30
  text "X" at 13038.9,767.85 h30
  text "2" at 13148.89,767.85 h30
  text "1" at 12833.89,766.36 h30
  text "3" at 13502.89,766.35 h30
  text "X" at 12074.9,620.17 h30
  text "RoHS" at 12202.89,620.17 h30
  text "OTHER" at 12847.29,620.17 h30
  text "PER ORDER" at 13244.35,620.17 h30
  text "ALL BOARDS MUST MEET OR EXCEED UL94-V0 REQUIREMENTS." at 10927.93,466.34 h30
  text "PCB MUST BEAR THE UL94V-0 UL REGISTERED MATERIAL ID NUMBER" at 10927.93,350.28 h30
  text "ADDITIONAL REQUIREMENTS:" at 10900.39,180.85 h30
  text "MICROSECTION:" at 10975.16,73.72 h30
  text "YES" at 11880.89,73.72 h30
  text "REQUIRED" at 12742.39,-70.61 h30
  text "BARE BOARD ELEC. TEST:" at 10975.16,-73.46 h30
  text "NONE" at 12280.89,-73.46 h30
  text "X" at 12624.39,-73.46 h30
  text "PER ORDER" at 13334.39,-73.46 h30
  text "XX MIL VIAS REQUIRE NON-CONDUCTIVE FILL AND PLANARIZE" at 11143.31,-278.41 h30
  text "XX MIL VIAS REQUIRE CONDUCTIVE FILL AND PLANARIZE" at 11151.31,-382.39 h30
  text "OUTER XX MIL TRACES REQUIRE 50 OHM SINGLE-ENDED IMPEDANCE" at 11150.32,-545.77 h30
  text "LAYER 2 & 3 (INNER LAYERS) XX MIL WIDE, XX MIL SPACE / TRACES REQUIRE 100 OHM DIFFERENTIAL IMPEDANCE" at 11142.32,-781.48 h30
  text ".Layer_Name" at 143.93,-2531.72 h30
M11 Gerber Information:
  lines w10: -725.07,-2603.4 5874.93,-2603.4 ; -725.07,-2400.06 5876.93,-2400.06 ; -725.07,-2196.73 -725.07,-2806.73 3279.93,-2806.73 5876.93,-2806.73 5876.93,-2196.73 -724.57,-2196.73 -724.57,-2806.73 850.93,-2806.73 ; 1739.93,-2806.73 1739.93,-2196.73 ; 3006.93,-2400.06 3006.93,-2196.73 ; 3846.93,-2400.06 3846.93,-2196.73 ; 4468.93,-2813.23 4468.93,-2610.4
  text "ALL ARTWORK VIEWED FROM TOP SIDE" at -661.57,-2328.9 h30
  text "BOARD #:" at 1814.93,-2328.9 h30
  text ".PRJ_Number" at 2360.43,-2328.9 h30
  text "REV:" at 3204.93,-2328.9 h30
  text ".PCB_Rev" at 3496.43,-2328.9 h30
  text "SVN REV:" at 4042.93,-2328.9 h30
  text ".VersionControl_RevNumber" at 4548.93,-2328.9 h30
  text "LAYER NAME =" at -661.57,-2531.72 h30
  text "TID #:" at 1814.93,-2532.23 h30
  text ".TID" at 2360.43,-2532.23 h30
  text "PLOT NAME =" at -661.57,-2737.56 h30
  text ".plot_File_Name" at 143.93,-2737.56 h30
  text "GENERATED    :" at 1816.93,-2737.56 h30
  text ".Print_Date" at 2686.43,-2737.56 h30
  text ".Print_Time" at 3415.43,-2737.56 h30
  text "TEXAS INSTRUMENTS" at 4679.93,-2737.56 h30
M12 Stackup:
  drawing of 295 lines, arcs and shapes, not listed
  text "Layer" at 9358.52,6246.71 h30
  text "Name" at 9573.48,6246.71 h30
  text "Material" at 10048.35,6246.71 h30
  text "Thickness" at 10488.24,6246.71 h30
  text "Constant" at 10823.15,6246.71 h30
  text "Board Layer Stack" at 11118.08,6246.71 h30
  text "Top Overlay" at 9573.48,6186.71 h30
  text "Top Solder" at 9573.48,6126.71 h30
  text "Solder Resist" at 10048.35,6126.71 h30
  text "0.40mil" at 10488.24,6126.71 h30
  text "3.5" at 10823.15,6126.71 h30
  text "1" at 9358.52,6066.71 h30
  text "Top Layer" at 9573.48,6066.71 h30
  text "2.76mil" at 10488.24,6066.71 h30
  text "Dielectric 1" at 9573.48,6006.71 h30
  text "PP-006" at 10048.35,6006.71 h30
  text "2.80mil" at 10488.24,6006.71 h30
  text "4.1" at 10823.15,6006.71 h30
  text "2" at 9358.52,5946.71 h30
  text "Layer 1" at 9573.48,5946.71 h30
  text "CF-004" at 10048.35,5946.71 h30
  text "1.38mil" at 10488.24,5946.71 h30
  text "Dielectric1" at 9573.48,5886.71 h30
  text "FR-4 High Tg" at 10048.35,5886.71 h30
  text "59.20mil" at 10488.24,5886.71 h30
  text "4.8" at 10823.15,5886.71 h30
  text "3" at 9358.52,5826.71 h30
  text "Layer 2" at 9573.48,5826.71 h30
  text "CF-004" at 10048.35,5826.71 h30
  text "1.38mil" at 10488.24,5826.71 h30
  text "Dielectric 2" at 9573.48,5766.71 h30
  text "PP-006" at 10048.35,5766.71 h30
  text "2.80mil" at 10488.24,5766.71 h30
  text "4.1" at 10823.15,5766.71 h30
  text "4" at 9358.52,5706.71 h30
  text "Bottom Layer" at 9573.48,5706.71 h30
  text "2.76mil" at 10488.24,5706.71 h30
  text "Bottom Solder" at 9573.48,5646.71 h30
  text "Solder Resist" at 10048.35,5646.71 h30
  text "0.40mil" at 10488.24,5646.71 h30
  text "3.5" at 10823.15,5646.71 h30
  text "Bottom Overlay" at 9573.48,5586.71 h30
  text ".Layer_Name" at 143.93,-2531.72 h30
M13 Component Bodies Top:
  text ".Layer_Name" at 143.93,-2531.72 h30
M14 Component Bodies Bottom:
  text ".Layer_Name" at 143.93,-2531.72 h30
M15 Courtyards Top:
  text ".Layer_Name" at 143.93,-2531.72 h30
M16 Courtyards Bottom:
  text ".Layer_Name" at 143.93,-2531.72 h30
Drill Drawing:
  circle w10: c5762.31,5904.37 r8.27
  circle w10: c5762.31,5904.37 r13.79
  circle w10: c5762.31,5594.13 r13.79
  lines w10: 5748.52,5214.94 5755.41,5214.94 5762.31,5208.05 5769.2,5214.94 5776.09,5214.94 5769.2,5221.84 5776.09,5228.73 5769.2,5228.73 5762.31,5235.63 5755.41,5228.73 5748.52,5228.73 5755.41,5221.84 5748.52,5214.94 ; 5748.52,5270.1 5762.31,5276.99 5776.09,5270.1 5769.2,5283.89 5776.09,5297.67 5762.31,5290.78 5748.52,5297.67 5755.41,5283.89 5748.52,5270.1 ; 5748.52,5332.15 5762.31,5339.04 5776.09,5332.15 5769.2,5345.93 5776.09,5359.72 5762.31,5352.83 5748.52,5359.72 5755.41,5345.93 5748.52,5332.15 ; 5748.52,5394.19 5748.52,5401.09 5755.41,5407.98 5748.52,5414.88 5748.52,5421.77 5755.41,5421.77 5762.31,5414.88 5769.2,5421.77 5776.09,5421.77 5776.09,5414.88 5769.2,5407.98 5776.09,5401.09 5776.09,5394.19 5769.2,5394.19 5762.31,5401.09 5755.41,5394.19 5748.52,5394.19 ; 5748.52,5463.14 5755.41,5463.14 5755.41,5456.24 5769.2,5456.24 5769.2,5463.14 5776.09,5463.14 5776.09,5476.92 5769.2,5476.92 5769.2,5483.82 5755.41,5483.82 5755.41,5476.92 5748.52,5476.92 5748.52,5463.14 ; 5748.52,5545.87 5776.09,5545.87 5762.31,5518.29 5748.52,5545.87 ; 5748.52,5642.39 5776.09,5642.39 5776.09,5669.96 5748.52,5669.96 5748.52,5642.39 ; 5748.52,5732.01 5776.09,5732.01 5762.31,5704.43 5748.52,5732.01 ; 5748.52,5780.27 5762.31,5766.48 5776.09,5780.27 5762.31,5794.06 5748.52,5780.27 ; 5748.52,5828.53 5776.09,5828.53 5776.09,5856.11 5748.52,5856.11 5748.52,5828.53 ; 5754.03,5337.66 5762.31,5341.8 5770.58,5337.66 5766.44,5345.93 5770.58,5354.21 5762.31,5350.07 5754.03,5354.21 5758.17,5345.93 5754.03,5337.66 ; 5754.03,5540.35 5770.58,5540.35 5762.31,5523.81 5754.03,5540.35 ; 5754.03,5834.05 5770.58,5834.05 5770.58,5850.59 5754.03,5850.59 5754.03,5834.05
  lines w12: 5721.95,5189.44 7336.57,5189.44 ; 5721.95,5934.01 7336.57,5934.01 ; 5890.78,5127.39 5890.78,5996.06 ; 6056.72,5127.39 6056.72,5996.06 ; 6374.93,5127.39 6374.93,5996.06 ; 6504.43,5127.39 6504.43,5996.06 ; 6691.94,5127.39 6691.94,5996.06 ; 7053.46,5127.39 7053.46,5996.06 ; 5721.95,5127.39 7336.57,5127.39 7336.57,5996.06 5721.95,5996.06 5721.95,5127.39
  text "Symbol" at 5759.18,5952.63 h36
  text "Quantity" at 5909.4,5952.63 h36
  text "Finished Hole Size" at 6075.33,5952.63 h36
  text "Plated" at 6393.54,5952.63 h36
  text "Hole Type" at 6523.05,5952.63 h36
  text "Drill Layer Pair" at 6710.56,5952.63 h36
  text "Hole Tolerance" at 7072.07,5952.63 h36
  text "4" at 5909.4,5890.58 h30
  text "133.86mil (3.400mm)" at 6075.33,5890.58 h30
  text "NPTH" at 6393.54,5890.58 h30
  text "Round" at 6523.05,5890.58 h30
  text "Top Layer - Bottom Layer" at 6710.56,5890.58 h30
  text "2668" at 5909.4,5828.53 h30
  text "7.87mil (0.200mm)" at 6075.33,5828.53 h30
  text "PTH" at 6393.54,5828.53 h30
  text "Round" at 6523.05,5828.53 h30
  text "Top Layer - Bottom Layer" at 6710.56,5828.53 h30
  text "1" at 5909.4,5766.48 h30
  text "20.00mil (0.508mm)" at 6075.33,5766.48 h30
  text "PTH" at 6393.54,5766.48 h30
  text "Round" at 6523.05,5766.48 h30
  text "Top Layer - Bottom Layer" at 6710.56,5766.48 h30
  text "6" at 5909.4,5704.43 h30
  text "35.43mil (0.900mm)" at 6075.33,5704.43 h30
  text "PTH" at 6393.54,5704.43 h30
  text "Round" at 6523.05,5704.43 h30
  text "Top Layer - Bottom Layer" at 6710.56,5704.43 h30
  text "60" at 5909.4,5642.39 h30
  text "40.00mil (1.016mm)" at 6075.33,5642.39 h30
  text "PTH" at 6393.54,5642.39 h30
  text "Round" at 6523.05,5642.39 h30
  text "Top Layer - Bottom Layer" at 6710.56,5642.39 h30
  text "8" at 5909.4,5580.34 h30
  text "40.16mil (1.020mm)" at 6075.33,5580.34 h30
  text "PTH" at 6393.54,5580.34 h30
  text "Round" at 6523.05,5580.34 h30
  text "Top Layer - Bottom Layer" at 6710.56,5580.34 h30
  text "44" at 5909.4,5518.29 h30
  text "42.91mil (1.090mm)" at 6075.33,5518.29 h30
  text "PTH" at 6393.54,5518.29 h30
  text "Round" at 6523.05,5518.29 h30
  text "Top Layer - Bottom Layer" at 6710.56,5518.29 h30
  text "2" at 5909.4,5456.24 h30
  text "49.21mil (1.250mm)" at 6075.33,5456.24 h30
  text "PTH" at 6393.54,5456.24 h30
  text "Round" at 6523.05,5456.24 h30
  text "Top Layer - Bottom Layer" at 6710.56,5456.24 h30
  text "8" at 5909.4,5394.19 h30
  text "63.00mil (1.600mm)" at 6075.33,5394.19 h30
  text "PTH" at 6393.54,5394.19 h30
  text "Round" at 6523.05,5394.19 h30
  text "Top Layer - Bottom Layer" at 6710.56,5394.19 h30
  text "2" at 5909.4,5332.15 h30
  text "20.00mil (0.508mm)" at 6075.33,5332.15 h30
  text "NPTH" at 6393.54,5332.15 h30
  text "Rectangle" at 6523.05,5332.15 h30
  text "Top Layer - Bottom Layer" at 6710.56,5332.15 h30
  text "61" at 5909.4,5270.1 h30
  text "20.00mil (0.508mm)" at 6075.33,5270.1 h30
  text "NPTH" at 6393.54,5270.1 h30
  text "Rectangle" at 6523.05,5270.1 h30
  text "Top Layer - Bottom Layer" at 6710.56,5270.1 h30
  text "2" at 5909.4,5208.05 h30
  text "324.80mil (8.250mm)" at 6075.33,5208.05 h30
  text "PTH" at 6393.54,5208.05 h30
  text "Slot" at 6523.05,5208.05 h30
  text "Top Layer - Bottom Layer" at 6710.56,5208.05 h30
  text "2866 Total" at 5909.4,5146 h30
  text "Slot definitions :" at 5759.18,5102.57 h30
  text "Routed Path Length" at 5984.13,5102.57 h30
  text "= Calculated from tool start centre position to tool end centre position." at 6253.51,5102.57 h30
  text "Hole Length" at 5984.13,5077.75 h30
  text "= Routed Path Length + Tool Size = Slot length as defined in the PCB layout" at 6153.79,5077.75 h30
  text ".Layer_Name" at 143.93,-2531.72 h30
M17 Embedded Cavity:
  text ".Layer_Name" at 143.93,-2531.72 h30
M18 Embedded Assembly:
  text ".Layer_Name" at 143.93,-2531.72 h30
M19 Embedded Keepout:
  text ".Layer_Name" at 143.93,-2531.72 h30

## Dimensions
-433.07,-2073.23 to 566.93,-2073.23 on M2 Board Dimensions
